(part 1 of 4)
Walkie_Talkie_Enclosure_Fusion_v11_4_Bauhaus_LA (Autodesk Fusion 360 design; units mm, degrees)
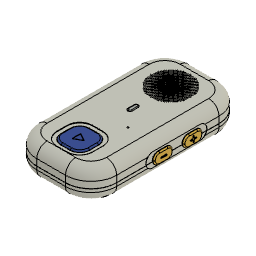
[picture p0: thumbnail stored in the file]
part number: 2026-09-08-11-09-09-888
part number: 2026-09-08-11-09-10-386
part number: 2026-09-08-11-09-34-228
part number: 2026-09-08-11-09-51-101
part number: 2026-09-08-11-09-52-372
part number: 2026-09-08-11-09-52-919
part number: 2026-09-08-11-09-54-602
part number: 2026-09-08-11-09-57-592
part number: 2026-09-08-11-09-59-896
part number: 2026-09-08-11-10-02-262
part number: 2026-09-08-11-10-02-642
part number: 2026-09-08-11-10-02-978
part number: 2026-09-08-11-10-03-318
part number: 2026-09-08-11-10-03-660
part number: 2026-09-08-11-10-04-003
part number: 2026-09-08-11-10-04-355
part number: 2026-09-08-11-10-04-734
part number: 2026-09-08-11-10-05-103
part number: 2026-09-08-11-10-05-446
part number: 2026-09-08-11-10-05-812
parameter "caseWidth" = 78 comment "Overall enclosure width"
parameter "caseHeight" = 150 comment "Overall enclosure height"
parameter "caseDepth" = 29.5 comment "Quiet Orb package depth with retained hardware clearance"
parameter "wallThickness" = 2.2 comment "Nominal enclosure wall"
parameter "frontBackSplit" = 15 comment "Centered front/back split line"
parameter "seamOverlap" = 1.25 comment "Continuous guarded lap-seam overlap"
parameter "seamHiddenRadialClearance" = 0.2 comment "Assembly clearance concealed behind lap seam"
parameter "speakerDiameter" = 40 comment "Measured supplied Samesky frame diameter"
parameter "pcbWidth" = 60.02 comment "Measured supplied PCB substrate width"
parameter "pcbHeight" = 80.02 comment "Measured supplied PCB substrate height"
parameter "fitClearance" = 0.25 comment "Per-side static FDM/SLS fit allowance"
parameter "slidingClearance" = 0.2 comment "Per-side moving-interface allowance"
parameter "buttonRestGap" = 0.14 comment "Cap-to-actuator clearance at rest"
parameter "sideSwitchMaxPretravel" = 0.45 comment "Omron B3F-3150 worst-case pretravel"
parameter "frontSwitchMaxPretravel" = 0.5 comment "Omron B3F-4000 worst-case pretravel"
parameter "sideButtonHardTravel" = 0.65 comment "Rest gap + maximum pretravel + 0.06 mm actuation margin"
parameter "frontButtonHardTravel" = 0.7 comment "Rest gap + maximum pretravel + 0.06 mm actuation margin"
parameter "sideActuatorCenterZ" = 16.7 comment "Measured installed B3F-3150 actuator center"
parameter "sideActuatorOpening" = 2.8 comment "Measured 2.40 mm actuator span plus sliding clearance"
parameter "ledBodyDiameter" = 5 comment "Measured Kingbright LED body"
parameter "ledFlangeDiameter" = 5.9 comment "Measured Kingbright LED flange"
parameter "batteryWidthMeasured" = 60.02 comment "Installed rigid battery body from supplied STL"
parameter "batteryHeightMeasured" = 36.02 comment "Installed rigid battery body from supplied STL"
parameter "batteryDepthMeasured" = 8.42 comment "Installed rigid battery body from supplied STL"
parameter "usbConnectorCenterY" = -21.0143 comment "Measured USB component center from supplied PCB STEP"
parameter "usbConnectorCenterZ" = 12.6764 comment "Measured USB component center from supplied PCB STEP"
parameter "usbOpeningWidth" = 9.38 comment "Measured connector Y span plus sliding clearance"
parameter "usbOpeningHeight" = 4.793 comment "Measured connector Z span plus sliding clearance"
parameter "usbLocalRecessDepth" = 2.7527 comment "Depth required for full 6.65 mm plug-shell seating"
parameter "minimumRibThickness" = 1.2 comment "Prototype FDM/SLS structural rib target"
parameter "minimumContactFillet" = 0.45 comment "No sharp rib at battery/film contact"
parameter "rearWordmarkWidth" = 42 comment "Text-only WALKIE ONE wordmark from supplied lockup"
parameter "rearWordmarkCenterY" = -52 comment "Final WALKIE ONE vertical position"
parameter "rearWordmarkDebossDepth" = 0.35 comment "Shallow printable rear engraving"
parameter "rearTaglineHeight" = 1.6 comment "Small upright Designed in Los Angeles lettering"
parameter "rearTaglineCenterY" = -58.5 comment "Centered origin line beneath WALKIE ONE"
parameter "rearTaglineDebossDepth" = 0.25 comment "Subordinate shallow rear engraving"
sketch "Outer Housing" plane through (0, 0, 0) normal (0, 0, 1) x axis (1, 0, 0)
  line L1 (14, -75) -> (-14, -75)
  line L2 (39, 50) -> (39, -50)
  line L3 (-14, 75) -> (14, 75)
  line L4 (-39, -50) -> (-39, 50)
  arc A1 centre (14, -50) radius 25 clockwise from (39, -50) to (14, -75)
  arc A2 centre (14, 50) radius 25 clockwise from (14, 75) to (39, 50)
  arc A3 centre (-14, 50) radius 25 clockwise from (-39, 50) to (-14, 75)
  arc A4 centre (-14, -50) radius 25 clockwise from (-14, -75) to (-39, -50)
extrude "Extrude1" new body sketch "Outer Housing" blind 15
fillet "Fillet1" radius 10
sketch "Front Cavity" plane through (0, 0, 0) normal (0, 0, 1) x axis (1, 0, 0)
  line L1 (14, -72.8) -> (-14, -72.8)
  line L2 (36.8, 50) -> (36.8, -50)
  line L3 (-14, 72.8) -> (14, 72.8)
  line L4 (-36.8, -50) -> (-36.8, 50)
  arc A1 centre (14, -50) radius 22.8 clockwise from (36.8, -50) to (14, -72.8)
  arc A2 centre (14, 50) radius 22.8 clockwise from (14, 72.8) to (36.8, 50)
  arc A3 centre (-14, 50) radius 22.8 clockwise from (-36.8, 50) to (-14, 72.8)
  arc A4 centre (-14, -50) radius 22.8 clockwise from (-14, -72.8) to (-36.8, -50)
extrude "Extrude2" new body sketch "Front Cavity" blind 13 from offset 2.2
fillet "Fillet2" radius 7.8
combine "Combine1"
sketch "Continuous Exterior Seam Guard Collar Sketch" plane through (0, 0, 0) normal (0, 0, 1) x axis (1, 0, 0)
  line L1 (14, -75) -> (-14, -75)
  line L2 (39, 50) -> (39, -50)
  line L3 (-14, 75) -> (14, 75)
  line L4 (-39, -50) -> (-39, 50)
  line L5 (14, -74) -> (-14, -74)
  line L6 (38, 50) -> (38, -50)
  line L7 (-14, 74) -> (14, 74)
  line L8 (-38, -50) -> (-38, 50)
  arc A1 centre (14, -50) radius 25 clockwise from (39, -50) to (14, -75)
  arc A2 centre (14, 50) radius 25 clockwise from (14, 75) to (39, 50)
  arc A3 centre (-14, 50) radius 25 clockwise from (-39, 50) to (-14, 75)
  arc A4 centre (-14, -50) radius 25 clockwise from (-14, -75) to (-39, -50)
  arc A5 centre (14, -50) radius 24 clockwise from (38, -50) to (14, -74)
  arc A6 centre (14, 50) radius 24 clockwise from (14, 74) to (38, 50)
  arc A7 centre (-14, 50) radius 24 clockwise from (-38, 50) to (-14, 74)
  arc A8 centre (-14, -50) radius 24 clockwise from (-14, -74) to (-38, -50)
extrude "Extrude3" add sketch "Continuous Exterior Seam Guard Collar Sketch" blind 1.65 from offset 14.6
sketch "Speaker Seat Solid Sketch" plane through (0, 0, 0) normal (0, 0, 1) x axis (1, 0, 0)
  circle C1 centre (0, 42) radius 23
extrude "Extrude4" add sketch "Speaker Seat Solid Sketch" blind 2.2 from offset 1.6
sketch "Speaker Seat Center Pocket Sketch" plane through (0, 0, 0) normal (0, 0, 1) x axis (1, 0, 0)
  circle C1 centre (0, 42) radius 20.3
extrude "Extrude5" cut sketch "Speaker Seat Center Pocket Sketch" blind 1.8 from offset 2.2
sketch "Speaker Terminal Hidden Relief Sketch" plane through (0, 0, 0) normal (0, 0, 1) x axis (1, 0, 0)
  line L1 (6.2, 18.45) -> (-6.2, 18.45)
  line L2 (6.5, 22.95) -> (6.5, 18.75)
  line L3 (-6.2, 23.25) -> (6.2, 23.25)
  line L4 (-6.5, 18.75) -> (-6.5, 22.95)
  arc A1 centre (6.2, 18.75) radius 0.3 clockwise from (6.5, 18.75) to (6.2, 18.45)
  arc A2 centre (6.2, 22.95) radius 0.3 clockwise from (6.2, 23.25) to (6.5, 22.95)
  arc A3 centre (-6.2, 22.95) radius 0.3 clockwise from (-6.5, 22.95) to (-6.2, 23.25)
  arc A4 centre (-6.2, 18.75) radius 0.3 clockwise from (-6.2, 18.45) to (-6.5, 18.75)
extrude "Extrude6" cut sketch "Speaker Terminal Hidden Relief Sketch" blind 1.9 from offset 2.2
sketch "Speaker Terminal Hidden Relief Sketch (1)" plane through (0, 0, 0) normal (0, 0, 1) x axis (1, 0, 0)
  line L1 (6.2, 58.75) -> (-6.2, 58.75)
  line L2 (6.5, 69.25) -> (6.5, 59.05)
  line L3 (-6.2, 69.55) -> (6.2, 69.55)
  line L4 (-6.5, 59.05) -> (-6.5, 69.25)
  arc A1 centre (6.2, 59.05) radius 0.3 clockwise from (6.5, 59.05) to (6.2, 58.75)
  arc A2 centre (6.2, 69.25) radius 0.3 clockwise from (6.2, 69.55) to (6.5, 69.25)
  arc A3 centre (-6.2, 69.25) radius 0.3 clockwise from (-6.5, 69.25) to (-6.2, 69.55)
  arc A4 centre (-6.2, 59.05) radius 0.3 clockwise from (-6.2, 58.75) to (-6.5, 59.05)
extrude "Extrude7" cut sketch "Speaker Terminal Hidden Relief Sketch (1)" blind 1.9 from offset 2.2
sketch "Speaker Snap Post Sketch" plane through (0, 0, 0) normal (0, 0, 1) x axis (1, 0, 0)
  circle C1 centre (15.27, 57.27) radius 1.5
extrude "Extrude8" add sketch "Speaker Snap Post Sketch" blind 5.75 from offset 2
sketch "Speaker Snap Lip Sketch" plane through (0, 0, 0) normal (0, 0, 1) x axis (1, 0, 0)
  circle C1 centre (15.27, 57.27) radius 2.1
extrude "Extrude9" add sketch "Speaker Snap Lip Sketch" blind 0.45 from offset 7.45
sketch "Speaker Snap Post Sketch (1)" plane through (0, 0, 0) normal (0, 0, 1) x axis (1, 0, 0)
  circle C1 centre (-15.27, 57.27) radius 1.5
extrude "Extrude10" add sketch "Speaker Snap Post Sketch (1)" blind 5.75 from offset 2
sketch "Speaker Snap Lip Sketch (1)" plane through (0, 0, 0) normal (0, 0, 1) x axis (1, 0, 0)
  circle C1 centre (-15.27, 57.27) radius 2.1
extrude "Extrude11" add sketch "Speaker Snap Lip Sketch (1)" blind 0.45 from offset 7.45
sketch "Speaker Snap Post Sketch (2)" plane through (0, 0, 0) normal (0, 0, 1) x axis (1, 0, 0)
  circle C1 centre (15.27, 26.73) radius 1.5
extrude "Extrude12" add sketch "Speaker Snap Post Sketch (2)" blind 5.75 from offset 2
sketch "Speaker Snap Lip Sketch (2)" plane through (0, 0, 0) normal (0, 0, 1) x axis (1, 0, 0)
  circle C1 centre (15.27, 26.73) radius 2.1
extrude "Extrude13" add sketch "Speaker Snap Lip Sketch (2)" blind 0.45 from offset 7.45
sketch "Speaker Snap Post Sketch (3)" plane through (0, 0, 0) normal (0, 0, 1) x axis (1, 0, 0)
  circle C1 centre (-15.27, 26.73) radius 1.5
extrude "Extrude14" add sketch "Speaker Snap Post Sketch (3)" blind 5.75 from offset 2
sketch "Speaker Snap Lip Sketch (3)" plane through (0, 0, 0) normal (0, 0, 1) x axis (1, 0, 0)
  circle C1 centre (-15.27, 26.73) radius 2.1
extrude "Extrude15" add sketch "Speaker Snap Lip Sketch (3)" blind 0.45 from offset 7.45
sketch "Orb W Speaker Grille 01" plane through (0, 0, 0) normal (0, 0, 1) x axis (1, 0, 0)
  curve K1 (0.32, 61.5759) -> (-0.32, 61.5759)
  curve K2 (0, 61.3559) -> (0, 61.7959)
  curve K3 (-5.8781, 60.6466) -> (-6.4853, 60.4443)
  curve K4 (-6.1121, 60.3368) -> (-6.2512, 60.7542)
  curve K5 (-4.8434, 60.6311) -> (-5.46, 60.4599)
  curve K6 (-5.0928, 60.3335) -> (-5.2106, 60.7575)
  curve K7 (-3.8089, 60.6149) -> (-4.4336, 60.4761)
  curve K8 (-4.0735, 60.3307) -> (-4.169, 60.7602)
  curve K9 (-2.7752, 60.5981) -> (-3.4065, 60.4929)
  curve K10 (-3.0547, 60.3285) -> (-3.127, 60.7625)
  curve K11 (-1.7424, 60.5808) -> (-2.3785, 60.5101)
  curve K12 (-2.0361, 60.3268) -> (-2.0847, 60.7641)
  curve K13 (-0.7109, 60.5632) -> (-1.3499, 60.5277)
  curve K14 (-1.0182, 60.3258) -> (-1.0426, 60.7651)
  curve K15 (0.32, 60.5455) -> (-0.32, 60.5455)
  curve K16 (0, 60.3255) -> (0, 60.7655)
  curve K17 (1.3499, 60.5277) -> (0.7109, 60.5632)
  curve K18 (1.0182, 60.3258) -> (1.0426, 60.7651)
  curve K19 (2.3785, 60.5101) -> (1.7424, 60.5808)
  curve K20 (2.0361, 60.3268) -> (2.0847, 60.7641)
  curve K21 (3.4065, 60.4929) -> (2.7752, 60.5981)
  curve K22 (3.0547, 60.3285) -> (3.127, 60.7625)
  curve K23 (4.4336, 60.4761) -> (3.8089, 60.6149)
  curve K24 (4.0735, 60.3307) -> (4.169, 60.7602)
  curve K25 (5.46, 60.4599) -> (4.8434, 60.6311)
  curve K26 (5.0928, 60.3335) -> (5.2106, 60.7575)
  curve K27 (6.4853, 60.4443) -> (5.8781, 60.6466)
  curve K28 (6.1121, 60.3368) -> (6.2512, 60.7542)
  curve K29 (-7.953, 59.6517) -> (-8.5321, 59.3792)
  curve K30 (-8.1489, 59.3164) -> (-8.3362, 59.7146)
  curve K31 (-6.9162, 59.6373) -> (-7.508, 59.3936)
  curve K32 (-7.1283, 59.3121) -> (-7.2959, 59.7189)
  curve K33 (-5.8799, 59.622) -> (-6.4834, 59.409)
  curve K34 (-6.1085, 59.308) -> (-6.2549, 59.7229)
  curve K35 (-4.8447, 59.6058) -> (-5.4587, 59.4252)
  curve K36 (-5.0896, 59.3044) -> (-5.2138, 59.7265)
  curve K37 (-3.8098, 59.5888) -> (-4.4328, 59.4422)
  curve K38 (-4.0709, 59.3013) -> (-4.1717, 59.7296)
  curve K39 (-2.7757, 59.5711) -> (-3.406, 59.4599)
  curve K40 (-3.0526, 59.2988) -> (-3.1291, 59.7321)
  curve K41 (-1.7426, 59.5529) -> (-2.3782, 59.4781)
  curve K42 (-2.0347, 59.297) -> (-2.0861, 59.734)
  curve K43 (-0.711, 59.5343) -> (-1.3499, 59.4967)
  curve K44 (-1.0175, 59.2959) -> (-1.0434, 59.7351)
  curve K45 (0.32, 59.5155) -> (-0.32, 59.5155)
  curve K46 (0, 59.2955) -> (0, 59.7355)
  curve K47 (1.3499, 59.4967) -> (0.711, 59.5343)
  curve K48 (1.0175, 59.2959) -> (1.0434, 59.7351)
  curve K49 (2.3782, 59.4781) -> (1.7426, 59.5529)
  curve K50 (2.0347, 59.297) -> (2.0861, 59.734)
  curve K51 (3.406, 59.4599) -> (2.7757, 59.5711)
  curve K52 (3.0526, 59.2988) -> (3.1291, 59.7321)
  curve K53 (4.4328, 59.4422) -> (3.8098, 59.5888)
  curve K54 (4.0709, 59.3013) -> (4.1717, 59.7296)
  curve K55 (5.4587, 59.4252) -> (4.8447, 59.6058)
  curve K56 (5.0896, 59.3044) -> (5.2138, 59.7265)
  curve K57 (6.4834, 59.409) -> (5.8799, 59.622)
  curve K58 (6.1085, 59.308) -> (6.2549, 59.7229)
  curve K59 (7.508, 59.3936) -> (6.9162, 59.6373)
  curve K60 (7.1283, 59.3121) -> (7.2959, 59.7189)
  curve K61 (8.5321, 59.3792) -> (7.953, 59.6517)
  curve K62 (8.1489, 59.3164) -> (8.3362, 59.7146)
  curve K63 (-10.0316, 58.6547) -> (-10.5743, 58.3154)
  curve K64 (-10.1863, 58.2985) -> (-10.4196, 58.6716)
  curve K65 (-8.9941, 58.642) -> (-9.5519, 58.3282)
  curve K66 (-9.1651, 58.2933) -> (-9.3808, 58.6768)
  curve K67 (-7.9563, 58.6282) -> (-8.5287, 58.3419)
  curve K68 (-8.1441, 58.2883) -> (-8.3409, 58.6818)
  curve K69 (-6.9189, 58.6133) -> (-7.5053, 58.3568)
  curve K70 (-7.1239, 58.2835) -> (-7.3003, 58.6866)
  curve K71 (-5.8821, 58.5974) -> (-6.4813, 58.3727)
  curve K72 (-6.1044, 58.2791) -> (-6.2589, 58.6911)
  curve K73 (-4.8462, 58.5805) -> (-5.4571, 58.3896)
  curve K74 (-5.0861, 58.2751) -> (-5.2173, 58.6951)
  curve K75 (-3.8108, 58.5627) -> (-4.4317, 58.4074)
  curve K76 (-4.0679, 58.2716) -> (-4.1746, 58.6985)
  curve K77 (-2.7763, 58.544) -> (-3.4054, 58.4261)
  curve K78 (-3.0503, 58.2688) -> (-3.1314, 58.7013)
  curve K79 (-1.7429, 58.5248) -> (-2.3779, 58.4453)
  curve K80 (-2.0331, 58.2668) -> (-2.0877, 58.7034)
  curve K81 (-0.711, 58.505) -> (-1.3498, 58.4651)
  curve K82 (-1.0167, 58.2655) -> (-1.0442, 58.7046)
  curve K83 (0.32, 58.4851) -> (-0.32, 58.4851)
  curve K84 (0, 58.2651) -> (0, 58.7051)
  curve K85 (1.3498, 58.4651) -> (0.711, 58.505)
  curve K86 (1.0167, 58.2655) -> (1.0442, 58.7046)
  curve K87 (2.3779, 58.4453) -> (1.7429, 58.5248)
  curve K88 (2.0331, 58.2668) -> (2.0877, 58.7034)
  curve K89 (3.4054, 58.4261) -> (2.7763, 58.544)
  curve K90 (3.0503, 58.2688) -> (3.1314, 58.7013)
  curve K91 (4.4317, 58.4074) -> (3.8108, 58.5627)
  curve K92 (4.0679, 58.2716) -> (4.1746, 58.6985)
  curve K93 (5.4571, 58.3896) -> (4.8462, 58.5805)
  curve K94 (5.0861, 58.2751) -> (5.2173, 58.6951)
  curve K95 (6.4813, 58.3727) -> (5.8821, 58.5974)
  curve K96 (6.1044, 58.2791) -> (6.2589, 58.6911)
  curve K97 (7.5053, 58.3568) -> (6.9189, 58.6133)
  curve K98 (7.1239, 58.2835) -> (7.3003, 58.6866)
  curve K99 (8.5287, 58.3419) -> (7.9563, 58.6282)
  curve K100 (8.1441, 58.2883) -> (8.3409, 58.6818)
  curve K101 (9.5519, 58.3282) -> (8.9941, 58.642)
  curve K102 (9.1651, 58.2933) -> (9.3808, 58.6768)
  curve K103 (10.5743, 58.3154) -> (10.0316, 58.6547)
  curve K104 (10.1863, 58.2985) -> (10.4196, 58.6716)
  curve K105 (-11.0753, 57.6439) -> (-11.5914, 57.2654)
  curve K106 (-11.2033, 57.2772) -> (-11.4635, 57.6321)
  curve K107 (-10.0367, 57.6321) -> (-10.5692, 57.2771)
  curve K108 (-10.1809, 57.2716) -> (-10.425, 57.6377)
  curve K109 (-8.9985, 57.6193) -> (-9.5474, 57.29)
  curve K110 (-9.1598, 57.266) -> (-9.3861, 57.6433)
  curve K111 (-7.9602, 57.6052) -> (-8.5249, 57.3041)
  curve K112 (-8.139, 57.2605) -> (-8.3461, 57.6488)
  curve K113 (-6.9221, 57.59) -> (-7.5021, 57.3193)
  curve K114 (-7.1191, 57.2553) -> (-7.3052, 57.654)
  curve K115 (-5.8846, 57.5735) -> (-6.4788, 57.3358)
  curve K116 (-6.1, 57.2504) -> (-6.2634, 57.6589)
  curve K117 (-4.8481, 57.5558) -> (-5.4553, 57.3535)
  curve K118 (-5.0815, 57.2441) -> (-5.2218, 57.6651)
  curve K119 (-3.8121, 57.5371) -> (-4.4305, 57.3722)
  curve K120 (-4.0619, 57.232) -> (-4.1806, 57.6773)
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extrude "Extrude16" cut sketch "Orb W Speaker Grille 01" blind 3.2
sketch "Orb W Speaker Grille 02" plane through (0, 0, 0) normal (0, 0, 1) x axis (1, 0, 0)
  curve K1 (3.4446, 51.1551) -> (2.7371, 51.3908)
  curve K2 (2.982, 50.9464) -> (3.1997, 51.5995)
  curve K3 (4.4599, 51.1225) -> (3.7826, 51.4234)
  curve K4 (3.9834, 50.9626) -> (4.2592, 51.5833)
  curve K5 (5.4729, 51.0945) -> (4.8305, 51.4514)
  curve K6 (4.9898, 50.9815) -> (5.3136, 51.5644)
  curve K7 (6.4849, 51.0708) -> (5.8785, 51.4751)
  curve K8 (6.0006, 51.0014) -> (6.3628, 51.5446)
  curve K9 (13.5764, 51.0099) -> (13.2121, 51.536)
  curve K10 (13.2115, 51.1464) -> (13.577, 51.3995)
  curve K11 (14.5973, 51.0038) -> (14.2512, 51.5421)
  curve K12 (14.2392, 51.154) -> (14.6093, 51.3919)
  curve K13 (15.6193, 50.9985) -> (15.29, 51.5474)
  curve K14 (15.266, 51.1598) -> (15.6433, 51.3861)
  curve K15 (16.642, 50.9941) -> (16.3282, 51.5519)
  curve K16 (16.2933, 51.1651) -> (16.6768, 51.3808)
  curve K17 (-17.3792, 50.5321) -> (-17.6517, 49.953)
  curve K18 (-17.3164, 50.1489) -> (-17.7146, 50.3362)
  curve K19 (-16.3419, 50.5287) -> (-16.6282, 49.9563)
  curve K20 (-16.2883, 50.1441) -> (-16.6818, 50.3409)
  curve K21 (-15.3041, 50.5249) -> (-15.6052, 49.9602)
  curve K22 (-15.2605, 50.139) -> (-15.6488, 50.3461)
  curve K23 (-14.2655, 50.5204) -> (-14.583, 49.9647)
  curve K24 (-14.2332, 50.1334) -> (-14.6152, 50.3517)
  curve K25 (-13.2265, 50.5151) -> (-13.5619, 49.97)
  curve K26 (-13.1917, 50.1179) -> (-13.5967, 50.3671)
  curve K27 (-5.8855, 50.4646) -> (-6.4778, 50.0204)
  curve K28 (-5.9789, 49.9721) -> (-6.3845, 50.513)
  curve K29 (-4.8355, 50.4402) -> (-5.4679, 50.0449)
  curve K30 (-4.969, 49.9503) -> (-5.3344, 50.5348)
  curve K31 (-3.785, 50.4107) -> (-4.4575, 50.0744)
  curve K32 (-3.9645, 49.9291) -> (-4.278, 50.556)
  curve K33 (-2.737, 50.3753) -> (-3.4447, 50.1098)
  curve K34 (-2.9661, 49.9101) -> (-3.2155, 50.575)
  curve K35 (-1.6923, 50.3346) -> (-2.4286, 50.1505)
  curve K36 (-1.9735, 49.8951) -> (-2.1473, 50.59)
  curve K37 (-0.6527, 50.2898) -> (-1.4081, 50.1953)
  curve K38 (-0.9857, 49.8852) -> (-1.0751, 50.5999)
  curve K39 (0.3806, 50.2425) -> (-0.3806, 50.2425)
  curve K40 (0, 49.882) -> (0, 50.603)
  curve K41 (1.4081, 50.1953) -> (0.6527, 50.2898)
  curve K42 (0.9857, 49.8852) -> (1.0751, 50.5999)
  curve K43 (2.4286, 50.1505) -> (1.6923, 50.3346)
  curve K44 (1.9735, 49.8951) -> (2.1473, 50.59)
  curve K45 (3.4447, 50.1098) -> (2.737, 50.3753)
  curve K46 (2.9661, 49.9101) -> (3.2155, 50.575)
  curve K47 (4.4575, 50.0744) -> (3.785, 50.4107)
  curve K48 (3.9645, 49.9291) -> (4.278, 50.556)
  curve K49 (5.4679, 50.0449) -> (4.8355, 50.4402)
  curve K50 (4.969, 49.9503) -> (5.3344, 50.5348)
  curve K51 (6.4778, 50.0204) -> (5.8855, 50.4646)
  curve K52 (5.9789, 49.9721) -> (6.3845, 50.513)
  curve K53 (13.5619, 49.97) -> (13.2265, 50.5151)
  curve K54 (13.1917, 50.1179) -> (13.5967, 50.3671)
  curve K55 (14.583, 49.9647) -> (14.2655, 50.5204)
  curve K56 (14.2332, 50.1334) -> (14.6152, 50.3517)
  curve K57 (15.6052, 49.9602) -> (15.3041, 50.5249)
  curve K58 (15.2605, 50.139) -> (15.6488, 50.3461)
  curve K59 (16.6282, 49.9563) -> (16.3419, 50.5287)
  curve K60 (16.2883, 50.1441) -> (16.6818, 50.3409)
  curve K61 (17.6517, 49.953) -> (17.3792, 50.5321)
  curve K62 (17.3164, 50.1489) -> (17.7146, 50.3362)
  curve K63 (-17.3936, 49.508) -> (-17.6373, 48.9162)
  curve K64 (-17.3121, 49.1283) -> (-17.7189, 49.2959)
  curve K65 (-16.3568, 49.5053) -> (-16.6133, 48.9189)
  curve K66 (-16.2835, 49.1239) -> (-16.6866, 49.3003)
  curve K67 (-15.3193, 49.5021) -> (-15.59, 48.9221)
  curve K68 (-15.2553, 49.1191) -> (-15.654, 49.3052)
  curve K69 (-14.2811, 49.4983) -> (-14.5673, 48.9259)
  curve K70 (-14.2216, 49.1108) -> (-14.6268, 49.3134)
  curve K71 (-13.24, 49.4985) -> (-13.5484, 48.9257)
  curve K72 (-13.1733, 49.0932) -> (-13.6151, 49.3311)
  curve K73 (-4.8442, 49.4318) -> (-5.4592, 48.9924)
  curve K74 (-4.9457, 48.9238) -> (-5.3576, 49.5004)
  curve K75 (-3.7911, 49.4007) -> (-4.4514, 49.0235)
  curve K76 (-3.9426, 48.8994) -> (-4.2999, 49.5248)
  curve K77 (-2.7392, 49.3628) -> (-3.4425, 49.0614)
  curve K78 (-2.9473, 48.8772) -> (-3.2344, 49.547)
  curve K79 (-1.6911, 49.3177) -> (-2.4297, 49.1066)
  curve K80 (-1.9594, 48.8588) -> (-2.1614, 49.5654)
  curve K81 (-0.6486, 49.2666) -> (-1.4122, 49.1576)
  curve K82 (-0.9781, 48.8457) -> (-1.0828, 49.5786)
  curve K83 (0.3864, 49.2121) -> (-0.3864, 49.2121)
  curve K84 (0, 48.8412) -> (0, 49.5831)
  curve K85 (1.4122, 49.1576) -> (0.6486, 49.2666)
  curve K86 (0.9781, 48.8457) -> (1.0828, 49.5786)
  curve K87 (2.4297, 49.1066) -> (1.6911, 49.3177)
  curve K88 (1.9594, 48.8588) -> (2.1614, 49.5654)
  curve K89 (3.4425, 49.0614) -> (2.7392, 49.3628)
  curve K90 (2.9473, 48.8772) -> (3.2344, 49.547)
  curve K91 (4.4514, 49.0235) -> (3.7911, 49.4007)
  curve K92 (3.9426, 48.8994) -> (4.2999, 49.5248)
  curve K93 (5.4592, 48.9924) -> (4.8442, 49.4318)
  curve K94 (4.9457, 48.9238) -> (5.3576, 49.5004)
  curve K95 (13.5484, 48.9257) -> (13.24, 49.4985)
  curve K96 (13.1733, 49.0932) -> (13.6151, 49.3311)
  curve K97 (14.5673, 48.9259) -> (14.2811, 49.4983)
  curve K98 (14.2216, 49.1108) -> (14.6268, 49.3134)
  curve K99 (15.59, 48.9221) -> (15.3193, 49.5021)
  curve K100 (15.2553, 49.1191) -> (15.654, 49.3052)
  curve K101 (16.6133, 48.9189) -> (16.3568, 49.5053)
  curve K102 (16.2835, 49.1239) -> (16.6866, 49.3003)
  curve K103 (17.6373, 48.9162) -> (17.3936, 49.508)
  curve K104 (17.3121, 49.1283) -> (17.7189, 49.2959)
  curve K105 (-18.4443, 48.4853) -> (-18.6466, 47.8781)
  curve K106 (-18.3368, 48.1121) -> (-18.7542, 48.2512)
  curve K107 (-17.409, 48.4834) -> (-17.622, 47.8799)
  curve K108 (-17.308, 48.1085) -> (-17.7229, 48.2549)
  curve K109 (-16.3727, 48.4813) -> (-16.5974, 47.8821)
  curve K110 (-16.2791, 48.1044) -> (-16.6911, 48.2589)
  curve K111 (-15.3358, 48.4788) -> (-15.5735, 47.8846)
  curve K112 (-15.2504, 48.1) -> (-15.6589, 48.2634)
  curve K113 (-14.2982, 48.4758) -> (-14.5503, 47.8876)
  curve K114 (-14.205, 48.0877) -> (-14.6435, 48.2756)
  curve K115 (-13.2556, 48.4819) -> (-13.5328, 47.8814)
  curve K116 (-13.1569, 48.0721) -> (-13.6315, 48.2912)
  curve K117 (-4.8584, 48.4261) -> (-5.445, 47.9372)
  curve K118 (-4.9196, 47.9033) -> (-5.3837, 48.4601)
  curve K119 (-3.8017, 48.3948) -> (-4.4409, 47.9686)
  curve K120 (-3.9172, 47.8756) -> (-4.3253, 48.4878)
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extrude "Extrude17" cut sketch "Orb W Speaker Grille 02" blind 3.2
sketch "Orb W Speaker Grille 03" plane through (0, 0, 0) normal (0, 0, 1) x axis (1, 0, 0)
  curve K1 (-13.494, 38.2029) -> (-13.2945, 37.5545)
  curve K2 (-13.1292, 37.9603) -> (-13.6592, 37.7972)
  curve K3 (-12.4741, 38.2097) -> (-12.2535, 37.5477)
  curve K4 (-12.0831, 37.9723) -> (-12.6445, 37.7852)
  curve K5 (-11.4554, 38.2143) -> (-11.2114, 37.5432)
  curve K6 (-11.0397, 37.9855) -> (-11.627, 37.772)
  curve K7 (-10.4383, 38.217) -> (-10.1676, 37.5404)
  curve K8 (-9.9992, 38.0002) -> (-10.6067, 37.7572)
  curve K9 (10.1676, 37.5404) -> (10.4383, 38.217)
  curve K10 (9.9992, 38.0002) -> (10.6067, 37.7572)
  curve K11 (11.2114, 37.5432) -> (11.4554, 38.2143)
  curve K12 (11.0397, 37.9855) -> (11.627, 37.772)
  curve K13 (12.2535, 37.5477) -> (12.4741, 38.2097)
  curve K14 (12.0831, 37.9723) -> (12.6445, 37.7852)
  curve K15 (13.2945, 37.5545) -> (13.494, 38.2029)
  curve K16 (13.1292, 37.9603) -> (13.6592, 37.7972)
  curve K17 (14.3342, 37.5638) -> (14.5142, 38.1937)
  curve K18 (14.1785, 37.949) -> (14.6699, 37.8085)
  curve K19 (15.3722, 37.5695) -> (15.5371, 38.1879)
  curve K20 (15.232, 37.9381) -> (15.6773, 37.8194)
  curve K21 (16.4074, 37.5683) -> (16.5627, 38.1892)
  curve K22 (16.2716, 37.9321) -> (16.6985, 37.8254)
  curve K23 (17.4422, 37.5672) -> (17.5888, 38.1902)
  curve K24 (17.3013, 37.9291) -> (17.7296, 37.8283)
  curve K25 (18.4761, 37.5664) -> (18.6149, 38.1911)
  curve K26 (18.3307, 37.9265) -> (18.7602, 37.831)
  curve K27 (-18.6311, 37.1566) -> (-18.4599, 36.54)
  curve K28 (-18.3335, 36.9072) -> (-18.7575, 36.7894)
  curve K29 (-17.6058, 37.1553) -> (-17.4252, 36.5413)
  curve K30 (-17.3044, 36.9104) -> (-17.7265, 36.7862)
  curve K31 (-16.5805, 37.1538) -> (-16.3896, 36.5429)
  curve K32 (-16.2751, 36.9139) -> (-16.6951, 36.7827)
  curve K33 (-15.5558, 37.1519) -> (-15.3535, 36.5447)
  curve K34 (-15.2441, 36.9185) -> (-15.6651, 36.7782)
  curve K35 (-14.5329, 37.1528) -> (-14.3155, 36.5438)
  curve K36 (-14.1908, 36.9316) -> (-14.6576, 36.765)
  curve K37 (-13.5146, 37.1613) -> (-13.2738, 36.5353)
  curve K38 (-13.142, 36.9453) -> (-13.6465, 36.7513)
  curve K39 (-12.4966, 37.1671) -> (-12.231, 36.5295)
  curve K40 (-12.0968, 36.9596) -> (-12.6308, 36.7371)
  curve K41 (-11.4798, 37.1705) -> (-11.1869, 36.5261)
  curve K42 (-11.0545, 36.975) -> (-11.6122, 36.7216)
  curve K43 (-10.4645, 37.1714) -> (-10.1414, 36.5252)
  curve K44 (-10.0158, 36.9919) -> (-10.5901, 36.7047)
  curve K45 (10.1414, 36.5252) -> (10.4645, 37.1714)
  curve K46 (10.0158, 36.9919) -> (10.5901, 36.7047)
  curve K47 (11.1869, 36.5261) -> (11.4798, 37.1705)
  curve K48 (11.0545, 36.975) -> (11.6122, 36.7216)
  curve K49 (12.231, 36.5295) -> (12.4966, 37.1671)
  curve K50 (12.0968, 36.9596) -> (12.6308, 36.7371)
  curve K51 (13.2738, 36.5353) -> (13.5146, 37.1613)
  curve K52 (13.142, 36.9453) -> (13.6465, 36.7513)
  curve K53 (14.3155, 36.5438) -> (14.5329, 37.1528)
  curve K54 (14.1908, 36.9316) -> (14.6576, 36.765)
  curve K55 (15.3535, 36.5447) -> (15.5558, 37.1519)
  curve K56 (15.2441, 36.9185) -> (15.6651, 36.7782)
  curve K57 (16.3896, 36.5429) -> (16.5805, 37.1538)
  curve K58 (16.2751, 36.9139) -> (16.6951, 36.7827)
  curve K59 (17.4252, 36.5413) -> (17.6058, 37.1553)
  curve K60 (17.3044, 36.9104) -> (17.7265, 36.7862)
  curve K61 (18.4599, 36.54) -> (18.6311, 37.1566)
  curve K62 (18.3335, 36.9072) -> (18.7575, 36.7894)
  curve K63 (-18.6466, 36.1219) -> (-18.4443, 35.5147)
  curve K64 (-18.3368, 35.8879) -> (-18.7542, 35.7488)
  curve K65 (-17.622, 36.1201) -> (-17.409, 35.5166)
  curve K66 (-17.308, 35.8915) -> (-17.7229, 35.7451)
  curve K67 (-16.5974, 36.1179) -> (-16.3727, 35.5187)
  curve K68 (-16.2791, 35.8956) -> (-16.6911, 35.7411)
  curve K69 (-15.5735, 36.1154) -> (-15.3358, 35.5212)
  curve K70 (-15.2504, 35.9) -> (-15.6589, 35.7366)
  curve K71 (-14.5503, 36.1124) -> (-14.2982, 35.5242)
  curve K72 (-14.205, 35.9123) -> (-14.6435, 35.7244)
  curve K73 (-13.5328, 36.1186) -> (-13.2556, 35.5181)
  curve K74 (-13.1569, 35.9279) -> (-13.6315, 35.7088)
  curve K75 (-12.5164, 36.1234) -> (-12.2112, 35.5132)
  curve K76 (-12.1124, 35.9441) -> (-12.6152, 35.6926)
  curve K77 (-11.501, 36.1256) -> (-11.1658, 35.511)
  curve K78 (-11.0716, 35.9611) -> (-11.5951, 35.6755)
  curve K79 (-10.4868, 36.1248) -> (-10.1191, 35.5118)
  curve K80 (-10.0343, 35.9795) -> (-10.5716, 35.6572)
  curve K81 (-9.4753, 36.1218) -> (-9.0706, 35.5148)
  curve K82 (-9.0007, 35.9998) -> (-9.5452, 35.6368)
  curve K83 (-0.3895, 35.8183) -> (0.3895, 35.8183)
  curve K84 (0, 36.1966) -> (0, 35.44)
  curve K85 (9.0706, 35.5148) -> (9.4753, 36.1218)
  curve K86 (9.0007, 35.9998) -> (9.5452, 35.6368)
  curve K87 (10.1191, 35.5118) -> (10.4868, 36.1248)
  curve K88 (10.0343, 35.9795) -> (10.5716, 35.6572)
  curve K89 (11.1658, 35.511) -> (11.501, 36.1256)
  curve K90 (11.0716, 35.9611) -> (11.5951, 35.6755)
  curve K91 (12.2112, 35.5132) -> (12.5164, 36.1234)
  curve K92 (12.1124, 35.9441) -> (12.6152, 35.6926)
  curve K93 (13.2556, 35.5181) -> (13.5328, 36.1186)
  curve K94 (13.1569, 35.9279) -> (13.6315, 35.7088)
  curve K95 (14.2982, 35.5242) -> (14.5503, 36.1124)
  curve K96 (14.205, 35.9123) -> (14.6435, 35.7244)
  curve K97 (15.3358, 35.5212) -> (15.5735, 36.1154)
  curve K98 (15.2504, 35.9) -> (15.6589, 35.7366)
  curve K99 (16.3727, 35.5187) -> (16.5974, 36.1179)
  curve K100 (16.2791, 35.8956) -> (16.6911, 35.7411)
  curve K101 (17.409, 35.5166) -> (17.622, 36.1201)
  curve K102 (17.308, 35.8915) -> (17.7229, 35.7451)
  curve K103 (18.4443, 35.5147) -> (18.6466, 36.1219)
  curve K104 (18.3368, 35.8879) -> (18.7542, 35.7488)
  curve K105 (-17.6373, 35.0838) -> (-17.3936, 34.492)
  curve K106 (-17.3121, 34.8717) -> (-17.7189, 34.7041)
  curve K107 (-16.6133, 35.0811) -> (-16.3568, 34.4947)
  curve K108 (-16.2835, 34.8761) -> (-16.6866, 34.6997)
  curve K109 (-15.59, 35.0779) -> (-15.3193, 34.4979)
  curve K110 (-15.2553, 34.8809) -> (-15.654, 34.6948)
  curve K111 (-14.5673, 35.0741) -> (-14.2811, 34.5017)
  curve K112 (-14.2216, 34.8892) -> (-14.6268, 34.6866)
  curve K113 (-13.5482, 35.0739) -> (-13.2402, 34.5018)
  curve K114 (-13.1736, 34.9067) -> (-13.6148, 34.6691)
  curve K115 (-12.533, 35.0779) -> (-12.1946, 34.4979)
  curve K116 (-12.1297, 34.9245) -> (-12.5979, 34.6513)
  curve K117 (-11.5186, 35.079) -> (-11.1482, 34.4968)
  curve K118 (-11.09, 34.9428) -> (-11.5768, 34.633)
  curve K119 (-10.5052, 35.0769) -> (-10.1007, 34.4989)
  curve K120 (-10.0539, 34.9622) -> (-10.552, 34.6136)
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extrude "Extrude18" cut sketch "Orb W Speaker Grille 03" blind 3.2
sketch "Orb W Speaker Grille 04" plane through (0, 0, 0) normal (0, 0, 1) x axis (1, 0, 0)
  curve K1 (3.8063, 27.4858) -> (4.4362, 27.6658)
  curve K2 (4.051, 27.8215) -> (4.1915, 27.3301)
  curve K3 (4.8472, 27.4671) -> (5.4562, 27.6845)
  curve K4 (5.0684, 27.8092) -> (5.235, 27.3424)
  curve K5 (5.8876, 27.4497) -> (6.4758, 27.7018)
  curve K6 (6.0877, 27.795) -> (6.2756, 27.3565)
  curve K7 (6.9259, 27.4327) -> (7.4983, 27.7189)
  curve K8 (7.1108, 27.7784) -> (7.3134, 27.3732)
  curve K9 (7.9647, 27.417) -> (8.5204, 27.7345)
  curve K10 (8.1334, 27.7668) -> (8.3517, 27.3848)
  curve K11 (9.0038, 27.4027) -> (9.5421, 27.7488)
  curve K12 (9.154, 27.7608) -> (9.3919, 27.3907)
  curve K13 (10.0426, 27.3898) -> (10.5633, 27.7618)
  curve K14 (10.1751, 27.7548) -> (10.4308, 27.3968)
  curve K15 (11.0818, 27.3781) -> (11.585, 27.7735)
  curve K16 (11.1974, 27.7488) -> (11.4693, 27.4028)
  curve K17 (12.1208, 27.3675) -> (12.6068, 27.784)
  curve K18 (12.2206, 27.7428) -> (12.507, 27.4087)
  curve K19 (-11.5914, 26.7346) -> (-11.0753, 26.3561)
  curve K20 (-11.2033, 26.7228) -> (-11.4635, 26.3679)
  curve K21 (-10.5692, 26.7229) -> (-10.0367, 26.3679)
  curve K22 (-10.1809, 26.7284) -> (-10.425, 26.3623)
  curve K23 (-9.5474, 26.71) -> (-8.9985, 26.3807)
  curve K24 (-9.1598, 26.734) -> (-9.3861, 26.3567)
  curve K25 (-8.5249, 26.6959) -> (-7.9602, 26.3948)
  curve K26 (-8.139, 26.7395) -> (-8.3461, 26.3512)
  curve K27 (-7.5021, 26.6807) -> (-6.9221, 26.41)
  curve K28 (-7.1191, 26.7447) -> (-7.3052, 26.346)
  curve K29 (-6.4788, 26.6642) -> (-5.8846, 26.4265)
  curve K30 (-6.1, 26.7496) -> (-6.2634, 26.3411)
  curve K31 (-5.4553, 26.6465) -> (-4.8481, 26.4442)
  curve K32 (-5.0815, 26.7559) -> (-5.2218, 26.3349)
  curve K33 (-4.4305, 26.6278) -> (-3.8121, 26.4629)
  curve K34 (-4.0619, 26.768) -> (-4.1806, 26.3227)
  curve K35 (-3.4046, 26.6081) -> (-2.7771, 26.4826)
  curve K36 (-3.0444, 26.7774) -> (-3.1372, 26.3134)
  curve K37 (-2.3776, 26.5876) -> (-1.7432, 26.5031)
  curve K38 (-2.0286, 26.7845) -> (-2.0923, 26.3062)
  curve K39 (-1.3507, 26.5667) -> (-0.7101, 26.524)
  curve K40 (-1.0142, 26.7884) -> (-1.0466, 26.3023)
  curve K41 (-0.3218, 26.5454) -> (0.3218, 26.5454)
  curve K42 (0, 26.7901) -> (0, 26.3006)
  curve K43 (0.7101, 26.524) -> (1.3507, 26.5667)
  curve K44 (1.0142, 26.7884) -> (1.0466, 26.3023)
  curve K45 (1.7432, 26.5031) -> (2.3776, 26.5876)
  curve K46 (2.0286, 26.7845) -> (2.0923, 26.3062)
  curve K47 (2.7771, 26.4826) -> (3.4046, 26.6081)
  curve K48 (3.0444, 26.7774) -> (3.1372, 26.3134)
  curve K49 (3.8121, 26.4629) -> (4.4305, 26.6278)
  curve K50 (4.0619, 26.768) -> (4.1806, 26.3227)
  curve K51 (4.8481, 26.4442) -> (5.4553, 26.6465)
  curve K52 (5.0815, 26.7559) -> (5.2218, 26.3349)
  curve K53 (5.8846, 26.4265) -> (6.4788, 26.6642)
  curve K54 (6.1, 26.7496) -> (6.2634, 26.3411)
  curve K55 (6.9221, 26.41) -> (7.5021, 26.6807)
  curve K56 (7.1191, 26.7447) -> (7.3052, 26.346)
  curve K57 (7.9602, 26.3948) -> (8.5249, 26.6959)
  curve K58 (8.139, 26.7395) -> (8.3461, 26.3512)
  curve K59 (8.9985, 26.3807) -> (9.5474, 26.71)
  curve K60 (9.1598, 26.734) -> (9.3861, 26.3567)
  curve K61 (10.0367, 26.3679) -> (10.5692, 26.7229)
  curve K62 (10.1809, 26.7284) -> (10.425, 26.3623)
  curve K63 (11.0753, 26.3561) -> (11.5914, 26.7346)
  curve K64 (11.2033, 26.7228) -> (11.4635, 26.3679)
  curve K65 (-10.5743, 25.6846) -> (-10.0316, 25.3453)
  curve K66 (-10.1863, 25.7015) -> (-10.4196, 25.3284)
  curve K67 (-9.5519, 25.6718) -> (-8.9941, 25.358)
  curve K68 (-9.1651, 25.7067) -> (-9.3808, 25.3232)
  curve K69 (-8.5287, 25.6581) -> (-7.9563, 25.3718)
  curve K70 (-8.1441, 25.7117) -> (-8.3409, 25.3182)
  curve K71 (-7.5053, 25.6432) -> (-6.9189, 25.3867)
  curve K72 (-7.1239, 25.7165) -> (-7.3003, 25.3134)
  curve K73 (-6.4813, 25.6273) -> (-5.8821, 25.4026)
  curve K74 (-6.1044, 25.7209) -> (-6.2589, 25.3089)
  curve K75 (-5.4571, 25.6104) -> (-4.8462, 25.4195)
  curve K76 (-5.0861, 25.7249) -> (-5.2173, 25.3049)
  curve K77 (-4.4317, 25.5926) -> (-3.8108, 25.4373)
  curve K78 (-4.0679, 25.7284) -> (-4.1746, 25.3015)
  curve K79 (-3.4054, 25.5739) -> (-2.7763, 25.456)
  curve K80 (-3.0503, 25.7312) -> (-3.1314, 25.2987)
  curve K81 (-2.3779, 25.5547) -> (-1.7429, 25.4752)
  curve K82 (-2.0331, 25.7332) -> (-2.0877, 25.2966)
  curve K83 (-1.3498, 25.5349) -> (-0.711, 25.495)
  curve K84 (-1.0167, 25.7345) -> (-1.0442, 25.2954)
  curve K85 (-0.32, 25.5149) -> (0.32, 25.5149)
  curve K86 (0, 25.7349) -> (0, 25.2949)
  curve K87 (0.711, 25.495) -> (1.3498, 25.5349)
  curve K88 (1.0167, 25.7345) -> (1.0442, 25.2954)
  curve K89 (1.7429, 25.4752) -> (2.3779, 25.5547)
  curve K90 (2.0331, 25.7332) -> (2.0877, 25.2966)
  curve K91 (2.7763, 25.456) -> (3.4054, 25.5739)
  curve K92 (3.0503, 25.7312) -> (3.1314, 25.2987)
  curve K93 (3.8108, 25.4373) -> (4.4317, 25.5926)
  curve K94 (4.0679, 25.7284) -> (4.1746, 25.3015)
  curve K95 (4.8462, 25.4195) -> (5.4571, 25.6104)
  curve K96 (5.0861, 25.7249) -> (5.2173, 25.3049)
  curve K97 (5.8821, 25.4026) -> (6.4813, 25.6273)
  curve K98 (6.1044, 25.7209) -> (6.2589, 25.3089)
  curve K99 (6.9189, 25.3867) -> (7.5053, 25.6432)
  curve K100 (7.1239, 25.7165) -> (7.3003, 25.3134)
  curve K101 (7.9563, 25.3718) -> (8.5287, 25.6581)
  curve K102 (8.1441, 25.7117) -> (8.3409, 25.3182)
  curve K103 (8.9941, 25.358) -> (9.5519, 25.6718)
  curve K104 (9.1651, 25.7067) -> (9.3808, 25.3232)
  curve K105 (10.0316, 25.3453) -> (10.5743, 25.6846)
  curve K106 (10.1863, 25.7015) -> (10.4196, 25.3284)
  curve K107 (-8.5321, 24.6208) -> (-7.953, 24.3483)
  curve K108 (-8.1489, 24.6836) -> (-8.3362, 24.2854)
  curve K109 (-7.508, 24.6064) -> (-6.9162, 24.3627)
  curve K110 (-7.1283, 24.6879) -> (-7.2959, 24.2811)
  curve K111 (-6.4834, 24.591) -> (-5.8799, 24.378)
  curve K112 (-6.1085, 24.692) -> (-6.2549, 24.2771)
  curve K113 (-5.4587, 24.5748) -> (-4.8447, 24.3942)
  curve K114 (-5.0896, 24.6956) -> (-5.2138, 24.2735)
  curve K115 (-4.4328, 24.5578) -> (-3.8098, 24.4112)
  curve K116 (-4.0709, 24.6987) -> (-4.1717, 24.2704)
  curve K117 (-3.406, 24.5401) -> (-2.7757, 24.4289)
  curve K118 (-3.0526, 24.7012) -> (-3.1291, 24.2679)
  curve K119 (-2.3782, 24.5219) -> (-1.7426, 24.4471)
  curve K120 (-2.0347, 24.703) -> (-2.0861, 24.266)
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extrude "Extrude19" cut sketch "Orb W Speaker Grille 04" blind 3.2
sketch "Orb W Speaker Grille 05" plane through (0, 0, 0) normal (0, 0, 1) x axis (1, 0, 0)
  curve K1 (-5.1517, 42.4043) -> (-5.1517, 41.5957)
  curve K2 (-4.7556, 42) -> (-5.5478, 42)
  curve K3 (5.1517, 41.5957) -> (5.1517, 42.4043)
  curve K4 (4.7556, 42) -> (5.5478, 42)
  curve K5 (9.273, 41.5961) -> (9.273, 42.4039)
  curve K6 (8.8966, 42) -> (9.6493, 42)
  curve K7 (-9.3165, 41.3614) -> (-9.2294, 40.5778)
  curve K8 (-8.9085, 41.0101) -> (-9.6374, 40.9291)
  curve K9 (-5.2323, 41.3728) -> (-5.071, 40.5663)
  curve K10 (-4.7564, 41.0486) -> (-5.547, 40.8905)
  curve K11 (-4.2208, 41.3678) -> (-4.0217, 40.5714)
  curve K12 (-3.7283, 41.0678) -> (-4.5142, 40.8713)
  curve K13 (-0.4263, 40.9696) -> (0.4263, 40.9696)
  curve K14 (0, 41.3955) -> (0, 40.5436)
  curve K15 (4.0217, 40.5714) -> (4.2208, 41.3678)
  curve K16 (3.7283, 41.0678) -> (4.5142, 40.8713)
  curve K17 (5.071, 40.5663) -> (5.2323, 41.3728)
  curve K18 (4.7564, 41.0486) -> (5.547, 40.8905)
  curve K19 (9.2294, 40.5778) -> (9.3165, 41.3614)
  curve K20 (8.9085, 41.0101) -> (9.6374, 40.9291)
  curve K21 (-9.3567, 40.3164) -> (-9.1892, 39.5627)
  curve K22 (-8.9233, 40.0173) -> (-9.6226, 39.8619)
  curve K23 (-5.3079, 40.33) -> (-4.9955, 39.5491)
  curve K24 (-4.7702, 40.0922) -> (-5.5331, 39.787)
  curve K25 (-4.3097, 40.3164) -> (-3.9328, 39.5628)
  curve K26 (-3.7504, 40.1251) -> (-4.4922, 39.7541)
  curve K27 (-0.4139, 39.9396) -> (0.4139, 39.9396)
  curve K28 (0, 40.352) -> (0, 39.5272)
  curve K29 (3.9328, 39.5628) -> (4.3097, 40.3164)
  curve K30 (3.7504, 40.1251) -> (4.4922, 39.7541)
  curve K31 (4.9955, 39.5491) -> (5.3079, 40.33)
  curve K32 (4.7702, 40.0922) -> (5.5331, 39.787)
  curve K33 (9.1892, 39.5627) -> (9.3567, 40.3164)
  curve K34 (8.9233, 40.0173) -> (9.6226, 39.8619)
  curve K35 (-8.4209, 38.2354) -> (-8.0641, 37.522)
  curve K36 (-7.9101, 38.045) -> (-8.575, 37.7125)
  curve K37 (-1.435, 37.9799) -> (-0.6259, 37.7776)
  curve K38 (-0.9306, 38.278) -> (-1.1303, 37.4794)
  curve K39 (0.6259, 37.7776) -> (1.435, 37.9799)
  curve K40 (0.9306, 38.278) -> (1.1303, 37.4794)
  curve K41 (8.0641, 37.522) -> (8.4209, 38.2354)
  curve K42 (7.9101, 38.045) -> (8.575, 37.7125)
  curve K43 (-8.448, 37.177) -> (-8.0371, 36.5196)
  curve K44 (-7.9388, 37.0382) -> (-8.5462, 36.6585)
  curve K45 (-1.4268, 36.9276) -> (-0.634, 36.769)
  curve K46 (-0.9527, 37.2367) -> (-1.1081, 36.4599)
  curve K47 (0.634, 36.769) -> (1.4268, 36.9276)
  curve K48 (0.9527, 37.2367) -> (1.1081, 36.4599)
  curve K49 (8.0371, 36.5196) -> (8.448, 37.177)
  curve K50 (7.9388, 37.0382) -> (8.5462, 36.6585)
  curve K51 (-2.4575, 35.9506) -> (-1.6633, 35.686)
  curve K52 (-1.9322, 36.2029) -> (-2.1886, 35.4337)
  curve K53 (1.6633, 35.686) -> (2.4575, 35.9506)
  curve K54 (1.9322, 36.2029) -> (2.1886, 35.4337)
  curve K55 (-7.4928, 35.0685) -> (-6.9315, 34.5072)
  curve K56 (-6.9553, 35.0447) -> (-7.4689, 34.5311)
  curve K57 (-2.4472, 34.8984) -> (-1.6736, 34.6773)
  curve K58 (-1.9547, 35.158) -> (-2.1662, 34.4178)
  curve K59 (1.6736, 34.6773) -> (2.4472, 34.8984)
  curve K60 (1.9547, 35.158) -> (2.1662, 34.4178)
  curve K61 (6.9315, 34.5072) -> (7.4928, 35.0685)
  curve K62 (6.9553, 35.0447) -> (7.4689, 34.5311)
  curve K63 (-7.5, 34.0094) -> (-6.9242, 33.5055)
  curve K64 (-6.9852, 34.0168) -> (-7.4391, 33.4981)
  curve K65 (-2.4379, 33.8519) -> (-1.6829, 33.6631)
  curve K66 (-1.9714, 34.1136) -> (-2.1495, 33.4014)
  curve K67 (1.6829, 33.6631) -> (2.4379, 33.8519)
  curve K68 (1.9714, 34.1136) -> (2.1495, 33.4014)
  curve K69 (6.9242, 33.5055) -> (7.5, 34.0094)
  curve K70 (6.9852, 34.0168) -> (7.4391, 33.4981)
  curve K71 (-7.5043, 32.9543) -> (-6.9199, 32.4998)
  curve K72 (-7.0115, 32.985) -> (-7.4127, 32.4691)
  curve K73 (-3.4681, 32.8528) -> (-2.7136, 32.6013)
  curve K74 (-2.9748, 33.0753) -> (-3.2069, 32.3788)
  curve K75 (2.7136, 32.6013) -> (3.4681, 32.8528)
  curve K76 (2.9748, 33.0753) -> (3.2069, 32.3788)
  curve K77 (6.9199, 32.4998) -> (7.5043, 32.9543)
  curve K78 (7.0115, 32.985) -> (7.4127, 32.4691)
  curve K79 (-6.5074, 31.8925) -> (-5.8559, 31.5016)
  curve K80 (-6.0104, 31.9826) -> (-6.353, 31.4115)
  curve K81 (-3.4539, 31.806) -> (-2.7277, 31.5881)
  curve K82 (-2.9924, 32.0253) -> (-3.1893, 31.3688)
  curve K83 (2.7277, 31.5881) -> (3.4539, 31.806)
  curve K84 (2.9924, 32.0253) -> (3.1893, 31.3688)
  curve K85 (5.8559, 31.5016) -> (6.5074, 31.8925)
  curve K86 (6.0104, 31.9826) -> (6.353, 31.4115)
  curve K87 (-5.4827, 30.8171) -> (-4.8207, 30.5162)
  curve K88 (-5.0216, 30.9529) -> (-5.2818, 30.3804)
  curve K89 (4.8207, 30.5162) -> (5.4827, 30.8171)
  curve K90 (5.0216, 30.9529) -> (5.2818, 30.3804)
  curve K91 (-10.054, 51.5495) -> (-10.5519, 50.9964)
  curve K92 (-10.0753, 51.068) -> (-10.5306, 51.4779)
  curve K93 (-9.0041, 51.5418) -> (-9.5418, 51.0041)
  curve K94 (-9.0454, 51.0454) -> (-9.5005, 51.5005)
  curve K95 (9.5418, 51.0041) -> (9.0041, 51.5418)
  curve K96 (9.0454, 51.0454) -> (9.5005, 51.5005)
  curve K97 (10.5519, 50.9964) -> (10.054, 51.5495)
  curve K98 (10.0753, 51.068) -> (10.5306, 51.4779)
  curve K99 (-7.9735, 49.5195) -> (-8.5116, 48.9047)
  curve K100 (-7.9657, 48.9699) -> (-8.5194, 49.4544)
  curve K101 (8.5116, 48.9047) -> (7.9735, 49.5195)
  curve K102 (7.9657, 48.9699) -> (8.5194, 49.4544)
  curve K103 (-7.987, 48.5224) -> (-8.4981, 47.8409)
  curve K104 (-7.9312, 47.9482) -> (-8.5539, 48.4152)
  curve K105 (8.4981, 47.8409) -> (7.987, 48.5224)
  curve K106 (7.9312, 47.9482) -> (8.5539, 48.4152)
  curve K107 (-10.1209, 47.5157) -> (-10.485, 46.7877)
  curve K108 (-9.9798, 46.9901) -> (-10.6261, 47.3133)
  curve K109 (0.4418, 47.1517) -> (-0.4418, 47.1517)
  curve K110 (0, 46.7188) -> (0, 47.5846)
  curve K111 (10.485, 46.7877) -> (10.1209, 47.5157)
  curve K112 (9.9798, 46.9901) -> (10.6261, 47.3133)
  curve K113 (-10.1551, 46.4909) -> (-10.4508, 45.7517)
  curve K114 (-9.9715, 45.9887) -> (-10.6344, 46.2538)
  curve K115 (-7.0039, 46.4857) -> (-7.4203, 45.7568)
  curve K116 (-6.8675, 45.9244) -> (-7.5567, 46.3182)
  curve K117 (-0.5902, 46.2314) -> (-1.4707, 46.0112)
  curve K118 (-0.9217, 45.6866) -> (-1.1391, 46.5559)
  curve K119 (1.4707, 46.0112) -> (0.5902, 46.2314)
  curve K120 (0.9217, 45.6866) -> (1.1391, 46.5559)
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extrude "Extrude20" cut sketch "Orb W Speaker Grille 05" blind 3.2
sketch "Orb W Speaker Grille 06" plane through (0, 0, 0) normal (0, 0, 1) x axis (1, 0, 0)
  curve K1 (-5.543, 32.9444) -> (-4.7604, 32.5097)
  curve K2 (-4.9545, 33.0821) -> (-5.3489, 32.372)
  curve K3 (-4.5201, 32.9043) -> (-3.7225, 32.5498)
  curve K4 (-3.959, 33.0922) -> (-4.2835, 32.3619)
  curve K5 (3.7225, 32.5498) -> (4.5201, 32.9043)
  curve K6 (3.959, 33.0922) -> (4.2835, 32.3619)
  curve K7 (4.7604, 32.5097) -> (5.543, 32.9444)
  curve K8 (4.9545, 33.0821) -> (5.3489, 32.372)
  closed curve K9 centre (-5.1517, 32.727)
  closed curve K10 centre (-4.1213, 32.727)
  closed curve K11 centre (4.1213, 32.727)
  closed curve K12 centre (5.1517, 32.727)
  point P3 (-4.7604, 32.5097)
  point P4 (-5.543, 32.9444)
  point P5 (-5.3489, 32.372)
  point P6 (-4.9545, 33.0821)
  point P8 (-3.7225, 32.5498)
  point P9 (-4.5201, 32.9043)
  point P10 (-4.2835, 32.3619)
  point P11 (-3.959, 33.0922)
  point P13 (4.5201, 32.9043)
  point P14 (3.7225, 32.5498)
  point P15 (4.2835, 32.3619)
  point P16 (3.959, 33.0922)
  point P18 (5.543, 32.9444)
  point P19 (4.7604, 32.5097)
  point P20 (5.3489, 32.372)
  point P21 (4.9545, 33.0821)
  coincident K9 P3
  coincident K9 P4
  coincident K9 P5
  coincident K9 P6
  coincident K10 P8
  coincident K10 P9
  coincident K10 P10
  coincident K10 P11
  coincident K11 P13
  coincident K11 P14
  coincident K11 P15
  coincident K11 P16
  coincident K12 P18
  coincident K12 P19
  coincident K12 P20
  coincident K12 P21
extrude "Extrude21" cut sketch "Orb W Speaker Grille 06" profile of K9 K10 K11 K12 blind 3.2
sketch "Quiet Orb Status Light Opening Sketch" plane through (0, 0, 0) normal (0, 0, 1) x axis (1, 0, 0)
  line L1 (0.05, -0.2) -> (-0.05, -0.2)
  line L2 (2.2, 8.05) -> (2.2, 1.95)
  line L3 (-0.05, 10.2) -> (0.05, 10.2)
  line L4 (-2.2, 1.95) -> (-2.2, 8.05)
  arc A1 centre (0.05, 1.95) radius 2.15 clockwise from (2.2, 1.95) to (0.05, -0.2)
  arc A2 centre (0.05, 8.05) radius 2.15 clockwise from (0.05, 10.2) to (2.2, 8.05)
  arc A3 centre (-0.05, 8.05) radius 2.15 clockwise from (-2.2, 8.05) to (-0.05, 10.2)
  arc A4 centre (-0.05, 1.95) radius 2.15 clockwise from (-0.05, -0.2) to (-2.2, 1.95)
extrude "Extrude22" cut sketch "Quiet Orb Status Light Opening Sketch" blind 3
sketch "Microphone Port Sketch" plane through (0, 0, 0) normal (0, 0, 1) x axis (1, 0, 0)
  circle C1 centre (-14, -14) radius 0.9
extrude "Extrude23" cut sketch "Microphone Port Sketch" blind 3.2
sketch "Sculpted Action Thumb Well Sketch" plane through (0, 0, 0) normal (0, 0, 1) x axis (1, 0, 0)
  line L1 (5, -64.5) -> (-5, -64.5)
  line L2 (17.5, -42) -> (17.5, -52)
  line L3 (-5, -29.5) -> (5, -29.5)
  line L4 (-17.5, -52) -> (-17.5, -42)
  arc A1 centre (5, -52) radius 12.5 clockwise from (17.5, -52) to (5, -64.5)
  arc A2 centre (5, -42) radius 12.5 clockwise from (5, -29.5) to (17.5, -42)
  arc A3 centre (-5, -42) radius 12.5 clockwise from (-17.5, -42) to (-5, -29.5)
  arc A4 centre (-5, -52) radius 12.5 clockwise from (-5, -64.5) to (-17.5, -52)
extrude "Extrude24" cut sketch "Sculpted Action Thumb Well Sketch" blind 0.58
sketch "Quiet Orb Action Button Opening Sketch" plane through (0, 0, 0) normal (0, 0, 1) x axis (1, 0, 0)
  line L1 (4.4, -61.1) -> (-4.4, -61.1)
  line L2 (14.1, -42.6) -> (14.1, -51.4)
  line L3 (-4.4, -32.9) -> (4.4, -32.9)
  line L4 (-14.1, -51.4) -> (-14.1, -42.6)
  arc A1 centre (4.4, -51.4) radius 9.7 clockwise from (14.1, -51.4) to (4.4, -61.1)
  arc A2 centre (4.4, -42.6) radius 9.7 clockwise from (4.4, -32.9) to (14.1, -42.6)
  arc A3 centre (-4.4, -42.6) radius 9.7 clockwise from (-14.1, -42.6) to (-4.4, -32.9)
  arc A4 centre (-4.4, -51.4) radius 9.7 clockwise from (-4.4, -61.1) to (-14.1, -51.4)
extrude "Extrude25" cut sketch "Quiet Orb Action Button Opening Sketch" blind 3
sketch "LED Guide Tube Solid Sketch" plane through (0, 0, 0) normal (0, 0, 1) x axis (1, 0, 0)
  circle C1 centre (0, 5) radius 4
extrude "Extrude26" add sketch "LED Guide Tube Solid Sketch" blind 8.9 from offset 1.8
sketch "LED Body Guide Bore Sketch" plane through (0, 0, 0) normal (0, 0, 1) x axis (1, 0, 0)
  circle C1 centre (0, 5) radius 2.65
extrude "Extrude27" cut sketch "LED Body Guide Bore Sketch" blind 7 from offset 2.05
sketch "LED Flange Pocket Sketch" plane through (0, 0, 0) normal (0, 0, 1) x axis (1, 0, 0)
  circle C1 centre (0, 5) radius 3.2
extrude "Extrude28" cut sketch "LED Flange Pocket Sketch" blind 2 from offset 9.05
sketch "LED Flange Flex Post Sketch" plane through (0, 0, 0) normal (0, 0, 1) x axis (1, 0, 0)
  line L1 (-3.57, 3.9) -> (-3.73, 3.9)
  line L2 (-3.15, 5.68) -> (-3.15, 4.32)
  line L3 (-3.73, 6.1) -> (-3.57, 6.1)
  line L4 (-4.15, 4.32) -> (-4.15, 5.68)
  arc A1 centre (-3.57, 4.32) radius 0.42 clockwise from (-3.15, 4.32) to (-3.57, 3.9)
  arc A2 centre (-3.57, 5.68) radius 0.42 clockwise from (-3.57, 6.1) to (-3.15, 5.68)
  arc A3 centre (-3.73, 5.68) radius 0.42 clockwise from (-4.15, 5.68) to (-3.73, 6.1)
  arc A4 centre (-3.73, 4.32) radius 0.42 clockwise from (-3.73, 3.9) to (-4.15, 4.32)
extrude "Extrude29" add sketch "LED Flange Flex Post Sketch" blind 2.3 from offset 8.8
sketch "LED Flange Flex Post Sketch (1)" plane through (0, 0, 0) normal (0, 0, 1) x axis (1, 0, 0)
  line L1 (3.73, 3.9) -> (3.57, 3.9)
  line L2 (4.15, 5.68) -> (4.15, 4.32)
  line L3 (3.57, 6.1) -> (3.73, 6.1)
  line L4 (3.15, 4.32) -> (3.15, 5.68)
  arc A1 centre (3.73, 4.32) radius 0.42 clockwise from (4.15, 4.32) to (3.73, 3.9)
  arc A2 centre (3.73, 5.68) radius 0.42 clockwise from (3.73, 6.1) to (4.15, 5.68)
  arc A3 centre (3.57, 5.68) radius 0.42 clockwise from (3.15, 5.68) to (3.57, 6.1)
  arc A4 centre (3.57, 4.32) radius 0.42 clockwise from (3.57, 3.9) to (3.15, 4.32)
extrude "Extrude30" add sketch "LED Flange Flex Post Sketch (1)" blind 2.3 from offset 8.8
sketch "LED Captive Flange Hook Sketch" plane through (0, 0, 0) normal (0, 0, 1) x axis (1, 0, 0)
  line L1 (-2.87, 3.9) -> (-3.73, 3.9)
  line L2 (-2.45, 5.68) -> (-2.45, 4.32)
  line L3 (-3.73, 6.1) -> (-2.87, 6.1)
  line L4 (-4.15, 4.32) -> (-4.15, 5.68)
  arc A1 centre (-2.87, 4.32) radius 0.42 clockwise from (-2.45, 4.32) to (-2.87, 3.9)
  arc A2 centre (-2.87, 5.68) radius 0.42 clockwise from (-2.87, 6.1) to (-2.45, 5.68)
  arc A3 centre (-3.73, 5.68) radius 0.42 clockwise from (-4.15, 5.68) to (-3.73, 6.1)
  arc A4 centre (-3.73, 4.32) radius 0.42 clockwise from (-3.73, 3.9) to (-4.15, 4.32)
extrude "Extrude31" add sketch "LED Captive Flange Hook Sketch" blind 0.5 from offset 10.55
sketch "LED Captive Flange Hook Sketch (1)" plane through (0, 0, 0) normal (0, 0, 1) x axis (1, 0, 0)
  line L1 (3.73, 3.9) -> (2.87, 3.9)
  line L2 (4.15, 5.68) -> (4.15, 4.32)
  line L3 (2.87, 6.1) -> (3.73, 6.1)
  line L4 (2.45, 4.32) -> (2.45, 5.68)
  arc A1 centre (3.73, 4.32) radius 0.42 clockwise from (4.15, 4.32) to (3.73, 3.9)
  arc A2 centre (3.73, 5.68) radius 0.42 clockwise from (3.73, 6.1) to (4.15, 5.68)
  arc A3 centre (2.87, 5.68) radius 0.42 clockwise from (2.45, 5.68) to (2.87, 6.1)
  arc A4 centre (2.87, 4.32) radius 0.42 clockwise from (2.87, 3.9) to (2.45, 4.32)
extrude "Extrude32" add sketch "LED Captive Flange Hook Sketch (1)" blind 0.5 from offset 10.55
